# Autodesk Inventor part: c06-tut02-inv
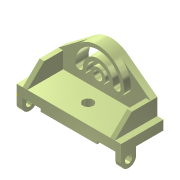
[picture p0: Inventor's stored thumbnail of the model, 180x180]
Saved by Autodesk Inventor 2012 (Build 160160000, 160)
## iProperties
Created: 2010-03
Part Number: c06-tut02-inv
Document SubType Name: Modeling
Designer: CADSoft
Density: 1 g/cm^3
Material: Default
Author: CADSoft
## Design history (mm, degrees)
sketch "Sketch1"
  geometry: 1 further point
sketch "Sketch2"
  geometry: L1 (0, 20)-(-222, 20); L2 (-222, 20)-(-222, 0); L3 (0, 0)-(0, 20); L4 (-171, 0)-(-171, -6); L5 (-171, -6)-(-51, -6); L6 (-51, -6)-(-51, 0); L7 (-222, 0)-(-171, 0); L8 (-51, 0)-(0, 0); 1 further point
  constraints: 16 end point, 4 horizontal, 4 vertical, 2 equal length, 1 coincident
  dimensions: "d0" = 20 distance of L3.start L1.start; "d1" = 26 distance between parallel lines of L5 L1; "d2" = 120 distance of L4.end L5.end; "d3" = 51 distance of L6.end L3.start
extrude "Extrusion1" new body sketch "Sketch2" distance "d4" = 90; taper "d5" = 0 deg
sketch "Sketch3"
  geometry: L1 (209, -20)-(209, -55); L2 (209, -55)-(144.749, -103.524); L3 (77.251, -103.524)-(13, -55); L4 (13, -55)-(13, -20); L5 (13, -20)-(209, -20); L6 (222, -20)-(0, -20) reference; L7 (222, 0)-(222, -20) reference; L8 (0, -20)-(0, 0) reference; A1 r 56 centre (111, -58.836) between (77.251, -103.524) and (144.749, -103.524)
  constraints: 10 end point, 2 equal length, 2 point on circle, 2 tangent, 2 vertical, 1 centre point, 1 horizontal, 1 point on line
  dimensions: "d6" = 35 distance of L1.start L1.end; "d7" = 13 distance between parallel lines of L7 L1; "d8" = 13 distance between parallel lines of L4 L8; "d9" = 56 radius of A1
extrude "Extrusion2" join sketch "Sketch3" distance "d10" = 14; taper "d11" = 0 deg
sketch "Sketch4"
  geometry: C1 r 16 at (111, 58.836); A1 r 56 centre (111, 58.836) between (144.749, 103.524) and (77.251, 103.524) reference; A2 r 24 centre (111, 58.836) between (135, 58.836) and (87, 58.836); A3 r 56 centre (111, 58.836) between (167, 58.836) and (55, 58.836); A4 r 16 centre (71, 58.836) between (55, 58.836) and (87, 58.836); A5 r 16 centre (151, 58.836) between (135, 58.836) and (167, 58.836); 1 further point
  constraints: 8 point on circle, 5 centre point, 4 tangent, 3 coincident, 2 horizontal alignment
  dimensions: "d12" = 56 radius of A3; "d14" = 24 radius of A2; "d15" = 32 diameter of C1
extrude "Extrusion3" join sketch "Sketch4" distance "d16" = 14; taper "d17" = 0 deg
sketch "Sketch5"
  geometry: C1 r 9 at (111, 58.836); A1 r 16 centre (151, 58.836) between (135, 58.836) and (167, 58.836) reference; A2 r 56 centre (111, 58.836) between (167, 58.836) and (55, 58.836) reference; A3 r 16 centre (71, 58.836) between (55, 58.836) and (87, 58.836) reference; A4 r 24 centre (111, 58.836) between (135, 58.836) and (87, 58.836) reference; A5 r 48 centre (111, 58.836) between (159, 58.836) and (63, 58.836); A6 r 8 centre (151, 58.836) between (143, 58.836) and (159, 58.836); A7 r 32 centre (111, 58.836) between (143, 58.836) and (79, 58.836); A8 r 8 centre (71, 58.836) between (63, 58.836) and (79, 58.836); 1 further point
  constraints: 8 point on circle, 5 centre point, 1 coincident, 3 other
  dimensions: "d18" = 8 radius of A8; "d19" = 18 diameter of C1
extrude "Extrusion4" cut sketch "Sketch5" stored distance "d20" = 14; taper "d21" = 0 deg
sketch "Sketch6"
  geometry: L1 (35, -90)-(0, -54); L2 (0, -54)-(0, -14); 2 further points
  constraints: 4 end point, 1 coincident
  dimensions: "d22" = 40 distance of L1.end L2.end
feature "Rib1" sketch "Sketch6" dims "d23" = 1, "d24" = 10, "d25" = 0
sketch "Sketch7"
  geometry: L1 (0, 0)-(0, 90) reference; L2 (0, 0)-(0, 32); L3 (0, 32)-(36, 32); L4 (36, 0)-(0, 0); C1 r 8 at (36, 16); A1 r 16 centre (36, 16) between (36, 0) and (36, 32)
  constraints: 6 end point, 2 centre point, 2 horizontal, 2 point on circle, 2 tangent, 1 coincident, 1 point on line
  dimensions: "d26" = 36 distance of L4.start L1.start; "d27" = 16 radius of A1; "d28" = 16 diameter of C1
extrude "Extrusion5" join sketch "Sketch7" distance "d29" = 12; taper "d30" = 0 deg
workplane "Work Plane1"
mirror "Mirror1"
hole "Hole1" diameter "d34" = 22; stored, may be unused: countersink angle "d38" = 90 deg, drill point angle "d40" = 118 deg; dims "d32" = 88, "d33" = 41, "d35" = 6, "d36" = 4, "d37" = 2, "d39" = 8
body "Solid1"
other parameters: "d31" = -111
